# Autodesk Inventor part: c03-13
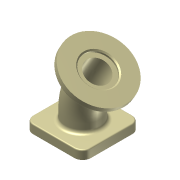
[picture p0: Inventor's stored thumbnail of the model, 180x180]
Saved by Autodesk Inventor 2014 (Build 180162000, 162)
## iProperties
Created: 2011-11
Part Number: c03-13
Material: Iron, Cast
Document SubType Name: Modeling
Designer: Thom Tremblay
Density: 7.25 g/cm^3
Mass: 1087.5 g
Surface Area: 260 cm^2
Volume: 150 cm^3
Appearance: Nylon 6
Author: Thom Tremblay
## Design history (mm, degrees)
sketch "Sketch1"
  geometry: L1 (50, -50)-(-50, -50); L2 (-50, -50)-(-50, 50); L3 (-50, 50)-(50, 50); L4 (50, 50)-(50, -50); C1 r 20 at (0, 0); C2 r 30 at (0, 0); 3 further points
  constraints: 8 end point, 2 centre point, 2 coincident, 2 midpoint, 2 parallel, 2 perpendicular, 1 horizontal, 1 horizontal alignment, 1 vertical alignment
  dimensions: "d0" = 100 distance of L2.end L3.end; "d3" = 40 diameter of C1; "d4" = 10 radial gap between concentric circles of C2 C1
extrude "Extrusion1" new body sketch "Sketch1" distance "d1" = 15; taper "d2" = 0 deg
sketch "Sketch2"
  geometry: L1 (0, 0)-(0, 30); L2 (12.794, 77.746)-(27.794, 103.727); A1 r 95.493 centre (95.493, 30) between (12.794, 77.746) and (0, 30)
  constraints: 4 end point, 2 point on circle, 2 tangent, 1 centre point, 1 vertical
  dimensions: "d5" = 30 distance of L1.start L1.end; "d7" = 50 dimension on A1; "d9" = 30 distance of L2.start L2.end; "d10" = 30 deg angle of L2 L1
sketch "Sketch3"
  geometry: L1 (12.794, 77.746)-(27.794, 103.727) reference; L2 (27.794, 103.727)-(75.425, 76.227); L3 (75.425, 76.227)-(70.425, 67.567); L4 (70.425, 67.567)-(22.794, 95.067); L5 (22.794, 95.067)-(27.794, 103.727); 2 further points
  constraints: 8 end point, 2 parallel, 2 perpendicular
  dimensions: "d11" = 110 diameter of L3 L5; "d13" = 10 distance between parallel lines of L2 L4
revolve "Revolution1" sketch "Sketch3" stored, may be unused: angle "d14" = 90 deg
sweep "Sweep1" dims "d15" = 0
sweep "Sweep2" dims "d16" = 0
sketch "Sketch4"
  geometry: C1 r 55 at (0, 0) reference; C2 r 27.5 at (0, 0); 1 further point
  constraints: 1 centre point, 1 coincident
  dimensions: "d17" = 55 diameter of C2
extrude "Extrusion2" cut sketch "Sketch4" distance "d18" = 5; taper "d19" = 0 deg
fillet "Fillet1" dims "d20" = 14
fillet "Fillet2" dims "d21" = 6, "d22" = 2
chamfer "Chamfer1" distance "d23" = 2; stored, may be unused: second distance "d24" = 2, angle "d25" = 45 deg
chamfer "Chamfer2" distance "d26" = 2; stored, may be unused: second distance "d27" = 4, angle "d28" = 45 deg
hole "Hole1" diameter "d31" = 10; stored, may be unused: countersink angle "d35" = 90 deg, drill point angle "d37" = 118 deg; dims "d29" = 30, "d30" = 10, "d32" = 6, "d33" = 4, "d34" = 2, "d36" = 8
body "Solid1"
